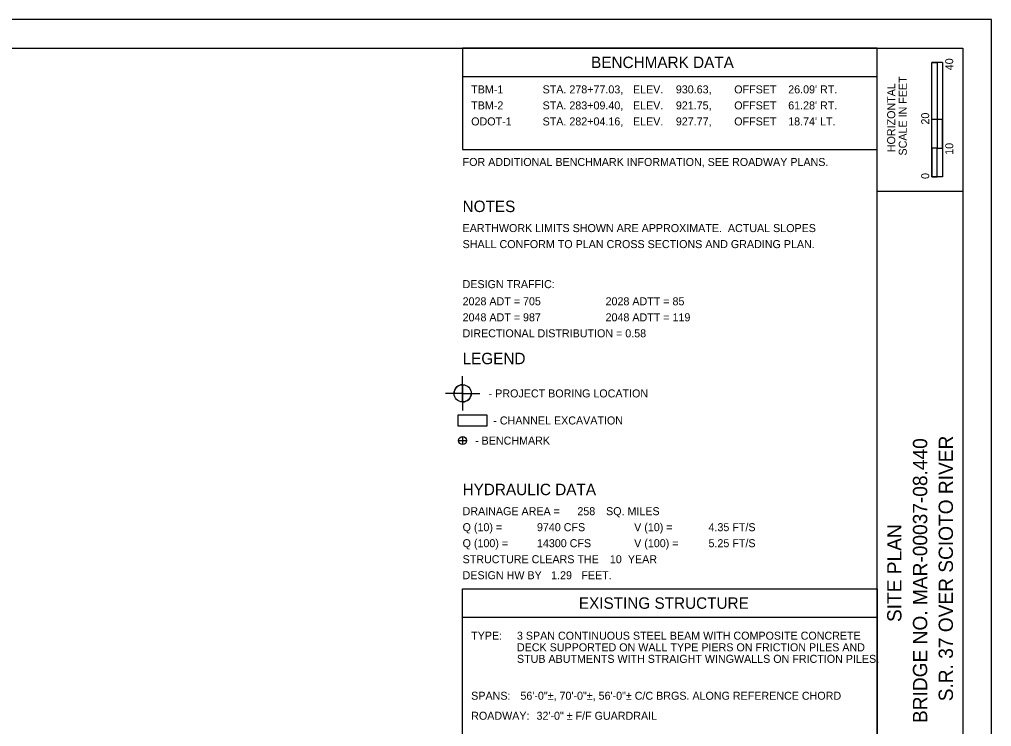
# Model space of a CAD drawing. Extents: x 0 to 34, y 0 to 22.
# Drawn here: x 17 to 34, y 9.64 to 22 of the extents above; entities that cross this region are included whole.
import ezdxf

# ---------------------------------------------------------------- set-up
doc = ezdxf.new("R2010")
doc.units = 0
for name, color, linetype in [('BR_P_Gen_Hatch', 7, 'Continuous'), ('DT_X_Break_Line', 7, 'Continuous'), ('DT_X_Contour_Major', 7, 'Continuous'), ('DT_X_Contour_Minor', 7, 'Continuous'), ('DT_X_Spot_Elev', 7, 'Continuous'), ('DT_X_Triangles', 7, 'Continuous'), ('SV_X_Control_Cells_Found', 7, 'Continuous')]:
    doc.layers.add(name, color=color, linetype=linetype)

# ---------------------------------------------------------------- blocks, each defined once
blk = doc.blocks.new('BM')
at = {"layer": 'SV_X_Control_Cells_Found'}
for p, q in [((-0.07, 0), (0.07, 0)), ((0, 0.07), (0, -0.07))]:
    blk.add_line(p, q, dxfattribs=at)
blk.add_circle((0, 0), 0.0705, dxfattribs=at)

msp = doc.modelspace()

# ---------------------------------------------------------------- linework, layer by layer
at = {"layer": 'BR_P_Gen_Hatch'}
msp.add_lwpolyline([(24.673, 15.088), (25.173, 15.088), (25.173, 14.888), (24.673, 14.888)], close=True, dxfattribs=at)
at = {"layer": 'DT_X_Contour_Major'}
msp.add_lwpolyline([(0, 0), (34, 0), (34, 22), (0, 22)], close=True, dxfattribs=at)
at = {"layer": 'DT_X_Contour_Minor'}
for p, q in [((24.75, 15.462), (24.75, 15.762)), ((24.75, 15.612), (24.75, 15.462)), ((24.75, 15.462), (24.45, 15.462)), ((24.75, 15.462), (24.6, 15.462)), ((24.75, 15.462), (24.75, 15.162)), ((24.75, 15.462), (25.05, 15.462)), ((24.75, 15.312), (24.75, 15.462)), ((24.75, 15.462), (24.9, 15.462))]:
    msp.add_line(p, q, dxfattribs=at)
msp.add_circle((24.75, 15.462), 0.15, dxfattribs=at)
for start, end in [(90, 180), (270, 360)]:
    msp.add_arc((24.75, 15.462), 0.15, start, end, dxfattribs=at)
at = {"layer": 'DT_X_Spot_Elev'}
for p, q in [((32, 0.5), (32, 21.5)), ((32, 19), (33.5, 19))]:
    msp.add_line(p, q, dxfattribs=at)
msp.add_lwpolyline([(1.5, 21.5), (33.5, 21.5), (33.5, 0.5), (1.5, 0.5)], close=True, dxfattribs=at)
at = {"layer": 'DT_X_Triangles'}
for p, q in [((32.957, 20.25), (32.957, 21.25)), ((32.957, 21.25), (33.05, 21.25)), ((32.957, 19.25), (32.957, 21.25)), ((33.144, 21.25), (32.957, 21.25)), ((33.05, 21.25), (33.051, 21.25)), ((33.051, 21.25), (33.051, 20.25)), ((33.144, 21.25), (33.144, 19.25)), ((24.75, 21), (32, 21)), ((33.051, 20.25), (32.957, 20.25)), ((33.143, 20.25), (33.05, 20.25)), ((33.05, 20.25), (33.05, 19.75)), ((33.143, 19.75), (33.143, 20.25)), ((33.05, 19.75), (32.957, 19.75)), ((32.957, 19.75), (32.957, 19.25)), ((33.05, 19.75), (33.143, 19.75)), ((33.05, 19.25), (33.05, 19.75)), ((33.144, 19.25), (32.957, 19.25)), ((32.957, 19.25), (33.05, 19.25)), ((32, 11.545), (24.75, 11.545))]:
    msp.add_line(p, q, dxfattribs=at)
for points in [[(32, 21.5), (24.75, 21.5), (24.75, 19.727), (32, 19.727)], [(24.673, 15.088), (25.173, 15.088), (25.173, 14.888), (24.673, 14.888)], [(24.75, 12.045), (32, 12.045), (32, 6.431), (24.75, 6.431)]]:
    msp.add_lwpolyline(points, close=True, dxfattribs=at)

# ---------------------------------------------------------------- block references
at = {"layer": 'DT_X_Break_Line'}
msp.add_blockref('BM', (24.75, 14.637), dxfattribs=at)

# ---------------------------------------------------------------- texts
at = {"layer": 'DT_X_Triangles'}
for s, height, p in [('BENCHMARK DATA', 0.2, (26.997, 21.15)), ('TBM-1', 0.14, (24.9, 20.707)), ('STA. 278+77.03,', 0.14, (26.149, 20.707)), ('ELEV.', 0.14, (27.729, 20.707)), ('930.63,', 0.14, (28.479, 20.707)), ('OFFSET', 0.14, (29.5, 20.707)), ("26.09' RT.", 0.14, (30.444, 20.707)), ('TBM-2', 0.14, (24.9, 20.427)), ('STA. 283+09.40,', 0.14, (26.149, 20.427)), ('ELEV.', 0.14, (27.729, 20.427)), ('921.75,', 0.14, (28.479, 20.427)), ('OFFSET', 0.14, (29.5, 20.427)), ("61.28' RT.", 0.14, (30.444, 20.427)), ('ODOT-1', 0.14, (24.9, 20.147)), ('STA. 282+04.16,', 0.14, (26.149, 20.147)), ('ELEV.', 0.14, (27.729, 20.147)), ('927.77,', 0.14, (28.479, 20.147)), ('OFFSET', 0.14, (29.5, 20.147)), ("18.74' LT.", 0.14, (30.444, 20.147)), ('FOR ADDITIONAL BENCHMARK INFORMATION, SEE ROADWAY PLANS.', 0.14, (24.75, 19.438)), ('NOTES', 0.2, (24.75, 18.632)), ('EARTHWORK LIMITS SHOWN ARE APPROXIMATE.  ACTUAL SLOPES', 0.14, (24.75, 18.282)), ('SHALL CONFORM TO PLAN CROSS SECTIONS AND GRADING PLAN.', 0.14, (24.75, 18.002)), ('DESIGN TRAFFIC:', 0.14, (24.75, 17.302)), ('2028 ADT = 705', 0.14, (24.75, 17.002)), ('2028 ADTT = 85', 0.14, (27.25, 17.002)), ('2048 ADT = 987', 0.14, (24.75, 16.722)), ('2048 ADTT = 119', 0.14, (27.25, 16.722)), ('DIRECTIONAL DISTRIBUTION =', 0.14, (24.75, 16.442)), ('DIRECTIONAL DISTRIBUTION = 0.58', 0.14, (24.75, 16.442)), ('LEGEND', 0.2, (24.75, 15.972)), ('- PROJECT BORING LOCATION', 0.14, (25.206, 15.391)), ('- CHANNEL EXCAVATION', 0.14, (25.287, 14.918)), ('- BENCHMARK', 0.14, (24.968, 14.566)), ('HYDRAULIC DATA', 0.2, (24.75, 13.682)), ('DRAINAGE AREA =', 0.14, (24.75, 13.332)), ('258', 0.14, (26.757, 13.332)), ('SQ. MILES', 0.14, (27.259, 13.332)), ('Q (10) =', 0.14, (24.75, 13.052)), ('9740 CFS', 0.14, (26.05, 13.052)), ('V (10) =', 0.14, (27.75, 13.052)), ('4.35 FT/S', 0.14, (29.05, 13.052)), ('Q (100) =', 0.14, (24.75, 12.772)), ('14300 CFS', 0.14, (26.05, 12.772)), ('V (100) =', 0.14, (27.75, 12.772)), ('5.25 FT/S', 0.14, (29.05, 12.772)), ('STRUCTURE CLEARS THE', 0.14, (24.75, 12.492)), ('10', 0.14, (27.325, 12.492)), ('YEAR', 0.14, (27.64, 12.492)), ('DESIGN HW BY', 0.14, (24.75, 12.212)), ('1.29', 0.14, (26.298, 12.212)), ('FEET.', 0.14, (26.827, 12.212)), ('EXISTING STRUCTURE', 0.2, (26.783, 11.695)), ('TYPE:', 0.14, (24.9, 11.155)), ('TYPE:', 0.14, (24.9, 11.155)), ('3 SPAN CONTINUOUS STEEL BEAM WITH COMPOSITE CONCRETE', 0.14, (25.7, 11.155)), ('DECK SUPPORTED ON WALL TYPE PIERS ON FRICTION PILES AND', 0.14, (25.7, 10.952)), ('STUB ABUTMENTS WITH STRAIGHT WINGWALLS ON FRICTION PILES.', 0.14, (25.7, 10.75)), ('SPANS:', 0.14, (24.9, 10.105)), ('SPANS:', 0.14, (24.9, 10.105)), ('56\'-0"±, 70\'-0"±, 56\'-0"± C/C BRGS. ALONG REFERENCE CHORD', 0.14, (25.761, 10.105)), ('ROADWAY:', 0.14, (24.9, 9.755)), ('ROADWAY:', 0.14, (24.9, 9.755)), ('32\'-0" ± F/F GUARDRAIL', 0.14, (26.042, 9.755))]:
    msp.add_text(s, height=height, dxfattribs=at).set_placement(p)
for s, height, p in [('40', 0.14, (33.33, 21.112)), ('SCALE IN FEET', 0.14, (32.517, 19.621)), ('HORIZONTAL', 0.14, (32.315, 19.679)), ('20', 0.14, (32.91, 20.162)), ('10', 0.14, (33.33, 19.633)), ('0', 0.14, (32.91, 19.211)), ('BRIDGE NO. MAR-00037-08.440', 0.25, (32.875, 9.698)), ('S.R. 37 OVER SCIOTO RIVER', 0.25, (33.325, 10.078)), ('SITE PLAN', 0.25, (32.425, 11.464))]:
    msp.add_text(s, height=height, rotation=90, dxfattribs=at).set_placement(p)

doc.saveas('drawing.dxf')
